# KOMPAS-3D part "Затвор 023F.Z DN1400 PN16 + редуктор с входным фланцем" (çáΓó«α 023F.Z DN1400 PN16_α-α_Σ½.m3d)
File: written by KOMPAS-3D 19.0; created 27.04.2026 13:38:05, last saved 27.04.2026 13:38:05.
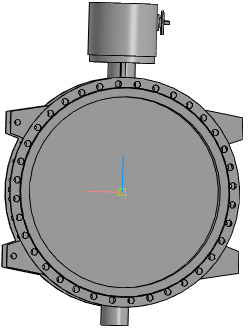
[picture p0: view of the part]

Document properties: Полное имя файла: ..\..\Затвор 023F.Z DN200-DN1600_редуктор с входным фланцем\Затвор 023F.Z DN1400 PN16 + редуктор с входным фланцем.a3d

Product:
- Part/product: Затвор 023F.Z DN1400 PN16 + редуктор с входным фланцем
    Масса: 3559.26

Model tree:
1. Операция без истории:1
